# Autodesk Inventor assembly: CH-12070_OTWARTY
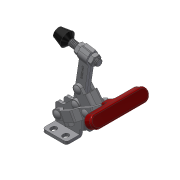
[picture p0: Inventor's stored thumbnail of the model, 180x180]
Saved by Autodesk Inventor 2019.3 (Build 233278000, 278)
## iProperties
Company: Î¢ÈíÖÐ¹ú
Created: 2015-08
Part Number: CH-12070_OTWARTY
Material: Ogólny
Description: STEP AP203
Document SubType Name: Assembly
Designer: CADENGINEERING4
Sending System: SolidWorks 2012
Preprocessor: SwSTEP 2.0
Title: CH-12070.STEP
Author: Î¢ÈíÓÃ»§
Revision Number: ÈÎºÎ
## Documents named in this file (9)
- D:\Vault_2016\Projekty\NASZ KATALOG\CLAMPTEK\STRONA\Vertical toggle clamp\CH-12070\CH-12070_OTWARTY.iam
- D:\Vault_2016\Projekty\NASZ KATALOG\CLAMPTEK\STEP FILES\Vertical toggle clamp\CH-12070\CH-12050-01 FLANGED BASE.ipt
- D:\Vault_2016\Projekty\NASZ KATALOG\CLAMPTEK\STEP FILES\Vertical toggle clamp\CH-12070\CH-12070-02 FIXED SPINDLE.ipt
- D:\Vault_2016\Projekty\NASZ KATALOG\CLAMPTEK\STEP FILES\Vertical toggle clamp\CH-12070\CH-12070-03 T-HANDLE.ipt
- D:\Vault_2016\Projekty\NASZ KATALOG\CLAMPTEK\STEP FILES\Vertical toggle clamp\CH-12070\CH-12050-07.ipt
- D:\Vault_2016\Projekty\NASZ KATALOG\CLAMPTEK\STEP FILES\Vertical toggle clamp\CH-12070\CH-12050-06.ipt
- D:\Vault_2016\Projekty\NASZ KATALOG\CLAMPTEK\STEP FILES\Vertical toggle clamp\CH-12070\CH-12050-04 CONNECTING-PLATE.ipt
- D:\Vault_2016\Projekty\NASZ KATALOG\CLAMPTEK\STEP FILES\Vertical toggle clamp\CH-12070\CH-FC-14134 Nut.ipt
- D:\Vault_2016\Projekty\NASZ KATALOG\CLAMPTEK\STEP FILES\Vertical toggle clamp\CH-12070\CH-FC-14134 SPINDLE SUPPLIED.ipt
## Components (11 placed, 8 different names)
1. CH-12050-01 FLANGED BASE_1
2. CH-12070-02 FIXED SPINDLE:2 — Zestawiające:5, Zestawiające:8, Zestawiające:17, Zestawiające:18, Zestawiające:19, Równoległe:1, Zestawiające:20
3. CH-12070-03 T-HANDLE:2 — Zestawiające:1, Zestawiające:2, Zestawiające:3, Zestawiające:9, Zestawiające:12, Zestawiające:13, Zestawiające:14
4. CH-12050-07:3 — Zestawiające:4, Zestawiające:5, Zestawiające:6, Zestawiające:7
5. CH-12050-07:4 — Zestawiające:20, Zestawiające:21
6. CH-12050-06:3 — Zestawiające:1, Zestawiające:2, Zestawiające:3
7. CH-12050-04 CONNECTING-PLATE:2 — Zestawiające:4, Zestawiające:6, Zestawiające:7, Zestawiające:8, Zestawiające:9, Zestawiające:10, Zestawiające:11, Zestawiające:21
8. CH-12050-06:4 — Zestawiające:10, Zestawiające:11, Zestawiające:12, Zestawiające:13, Zestawiające:14
9. CH-FC-14134 Nut:3 — Zestawiające:16, Zestawiające:17, Zestawiające:18
10. CH-FC-14134 SPINDLE SUPPLIED:2 — Zestawiające:15, Równoległe:1
11. CH-FC-14134 Nut:4 — Zestawiające:15, Zestawiające:16, Zestawiające:19
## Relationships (22: Mate 21, Flush 1)
- Zestawiające:1 [Mate]: CH-12070-03 T-HANDLE:2 ↔ CH-12050-06:3
- Zestawiające:2 [Mate]: CH-12070-03 T-HANDLE:2 ↔ CH-12050-06:3
- Zestawiające:3 [Mate]: CH-12070-03 T-HANDLE:2 ↔ CH-12050-06:3
- Zestawiające:4 [Mate]: CH-12050-07:3 ↔ CH-12050-04 CONNECTING-PLATE:2
- Zestawiające:5 [Mate]: CH-12070-02 FIXED SPINDLE:2 ↔ CH-12050-07:3
- Zestawiające:6 [Mate]: CH-12050-07:3 ↔ CH-12050-04 CONNECTING-PLATE:2
- Zestawiające:7 [Mate]: CH-12050-07:3 ↔ CH-12050-04 CONNECTING-PLATE:2
- Zestawiające:8 [Mate]: CH-12070-02 FIXED SPINDLE:2 ↔ CH-12050-04 CONNECTING-PLATE:2
- Zestawiające:9 [Mate]: CH-12070-03 T-HANDLE:2 ↔ CH-12050-04 CONNECTING-PLATE:2
- Zestawiające:10 [Mate]: CH-12050-04 CONNECTING-PLATE:2 ↔ CH-12050-06:4
- Zestawiające:11 [Mate]: CH-12050-04 CONNECTING-PLATE:2 ↔ CH-12050-06:4
- Zestawiające:12 [Mate]: CH-12070-03 T-HANDLE:2 ↔ CH-12050-06:4
- Zestawiające:13 [Mate]: CH-12070-03 T-HANDLE:2 ↔ CH-12050-06:4
- Zestawiające:14 [Mate]: CH-12070-03 T-HANDLE:2 ↔ CH-12050-06:4
- Zestawiające:15 [Mate]: CH-FC-14134 SPINDLE SUPPLIED:2 ↔ CH-FC-14134 Nut:4
- Zestawiające:16 [Mate]: CH-FC-14134 Nut:3 ↔ CH-FC-14134 Nut:4
- Zestawiające:17 [Mate]: CH-12070-02 FIXED SPINDLE:2 ↔ CH-FC-14134 Nut:3
- Zestawiające:18 [Mate]: CH-12070-02 FIXED SPINDLE:2 ↔ CH-FC-14134 Nut:3
- Zestawiające:19 [Mate]: CH-12070-02 FIXED SPINDLE:2 ↔ CH-FC-14134 Nut:4
- Równoległe:1 [Flush]: CH-12070-02 FIXED SPINDLE:2 ↔ CH-FC-14134 SPINDLE SUPPLIED:2
- Zestawiające:20 [Mate]: CH-12070-02 FIXED SPINDLE:2 ↔ CH-12050-07:4
- Zestawiające:21 [Mate]: CH-12050-07:4 ↔ CH-12050-04 CONNECTING-PLATE:2
